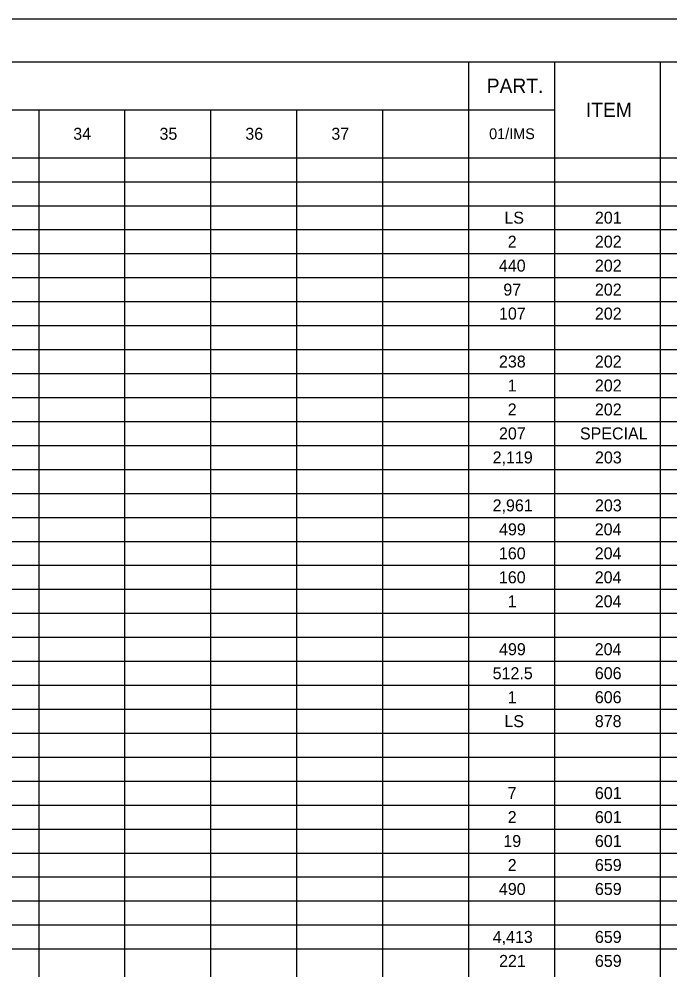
# Model space of a CAD drawing. Extents: x 0 to 34, y 0 to 22.
# Drawn here: x 9.31 to 16.92, y 10.89 to 22 of the extents above; entities that cross this region are included whole.
import ezdxf

# ---------------------------------------------------------------- set-up
doc = ezdxf.new("R2010")
doc.units = 0
for name, color, linetype in [('SH_Border', 7, 'Continuous'), ('SH_Cut_Line', 7, 'Continuous'), ('SH_Data', 7, 'Continuous'), ('SH_Text', 7, 'Continuous')]:
    doc.layers.add(name, color=color, linetype=linetype)

msp = doc.modelspace()

# ---------------------------------------------------------------- linework, layer by layer
at = {"layer": 'SH_Border'}
msp.add_lwpolyline([(1.5, 21.5), (33.5, 21.5), (33.5, 0.5), (1.5, 0.5)], close=True, dxfattribs=at)
at = {"layer": 'SH_Cut_Line'}
msp.add_lwpolyline([(0, 0), (34, 0), (34, 22), (0, 22)], close=True, dxfattribs=at)
at = {"layer": 'SH_Data'}
for p, q in [((1.5, 21.5), (32.004, 21.5)), ((14.561, 21.5), (14.561, 0.5)), ((15.566, 21.5), (15.566, 0.5)), ((16.801, 21.5), (16.801, 0.5)), ((1.5, 20.94), (15.566, 20.94)), ((9.538, 20.94), (9.538, 0.5)), ((10.542, 20.94), (10.542, 0.5)), ((11.547, 20.94), (11.547, 0.5)), ((12.552, 20.94), (12.552, 0.5)), ((13.556, 20.94), (13.556, 0.5)), ((1.5, 20.38), (32.004, 20.38)), ((1.5, 20.1), (32.004, 20.1)), ((1.5, 19.82), (32.004, 19.82)), ((1.5, 19.54), (32.004, 19.54)), ((1.5, 19.26), (32.004, 19.26)), ((1.5, 18.98), (32.004, 18.98)), ((1.5, 18.7), (32.004, 18.7)), ((1.5, 18.42), (32.004, 18.42)), ((1.5, 18.14), (32.004, 18.14)), ((1.5, 17.86), (32.004, 17.86)), ((1.5, 17.58), (32.004, 17.58)), ((1.5, 17.3), (32.004, 17.3)), ((1.5, 17.02), (32.004, 17.02)), ((1.5, 16.74), (32.004, 16.74)), ((1.5, 16.46), (32.004, 16.46)), ((1.5, 16.18), (32.004, 16.18)), ((1.5, 15.9), (32.004, 15.9)), ((1.5, 15.62), (32.004, 15.62)), ((1.5, 15.34), (32.004, 15.34)), ((1.5, 15.06), (32.004, 15.06)), ((1.5, 14.78), (32.004, 14.78)), ((1.5, 14.5), (32.004, 14.5)), ((1.5, 14.22), (32.004, 14.22)), ((1.5, 13.94), (32.004, 13.94)), ((1.5, 13.66), (32.004, 13.66)), ((1.5, 13.38), (32.004, 13.38)), ((1.5, 13.1), (32.004, 13.1)), ((1.5, 12.82), (32.004, 12.82)), ((1.5, 12.54), (32.004, 12.54)), ((1.5, 12.26), (32.004, 12.26)), ((1.5, 11.98), (32.004, 11.98)), ((1.5, 11.7), (32.004, 11.7)), ((1.5, 11.42), (32.004, 11.42)), ((1.5, 11.14), (32.004, 11.14))]:
    msp.add_line(p, q, dxfattribs=at)

# ---------------------------------------------------------------- texts
at = {"layer": 'SH_Text'}
for s, height, p in [('PART.', 0.168, (14.774, 21.136)), ('ITEM', 0.168, (15.933, 20.856)), ('34', 0.14, (9.942, 20.59)), ('35', 0.14, (10.95, 20.59)), ('36', 0.14, (11.953, 20.59)), ('37', 0.14, (12.958, 20.59)), ('01/IMS', 0.126, (14.802, 20.597)), ('LS', 0.14, (14.98, 19.61)), ('201', 0.14, (16.038, 19.61)), ('2', 0.14, (15.019, 19.33)), ('202', 0.14, (16.038, 19.33)), ('440', 0.14, (14.916, 19.05)), ('202', 0.14, (16.038, 19.05)), ('97', 0.14, (14.968, 18.77)), ('202', 0.14, (16.038, 18.77)), ('107', 0.14, (14.917, 18.49)), ('202', 0.14, (16.038, 18.49)), ('238', 0.14, (14.917, 17.93)), ('202', 0.14, (16.038, 17.93)), ('1', 0.14, (15.019, 17.65)), ('202', 0.14, (16.038, 17.65)), ('2', 0.14, (15.019, 17.37)), ('202', 0.14, (16.038, 17.37)), ('207', 0.14, (14.917, 17.09)), ('SPECIAL', 0.14, (15.863, 17.09)), ('2,119', 0.14, (14.843, 16.81)), ('203', 0.14, (16.039, 16.81)), ('2,961', 0.14, (14.843, 16.25)), ('203', 0.14, (16.039, 16.25)), ('499', 0.14, (14.918, 15.97)), ('204', 0.14, (16.036, 15.97)), ('160', 0.14, (14.916, 15.69)), ('204', 0.14, (16.036, 15.69)), ('160', 0.14, (14.916, 15.41)), ('204', 0.14, (16.036, 15.41)), ('1', 0.14, (15.019, 15.13)), ('204', 0.14, (16.036, 15.13)), ('499', 0.14, (14.918, 14.57)), ('204', 0.14, (16.036, 14.57)), ('512.5', 0.14, (14.843, 14.29)), ('606', 0.14, (16.037, 14.29)), ('1', 0.14, (15.019, 14.01)), ('606', 0.14, (16.037, 14.01)), ('LS', 0.14, (14.98, 13.73)), ('878', 0.14, (16.037, 13.73)), ('7', 0.14, (15.018, 12.89)), ('601', 0.14, (16.038, 12.89)), ('2', 0.14, (15.019, 12.61)), ('601', 0.14, (16.038, 12.61)), ('19', 0.14, (14.968, 12.33)), ('601', 0.14, (16.038, 12.33)), ('2', 0.14, (15.019, 12.05)), ('659', 0.14, (16.038, 12.05)), ('490', 0.14, (14.916, 11.77)), ('659', 0.14, (16.038, 11.77)), ('4,413', 0.14, (14.844, 11.21)), ('659', 0.14, (16.038, 11.21)), ('221', 0.14, (14.918, 10.93)), ('659', 0.14, (16.038, 10.93))]:
    msp.add_text(s, height=height, dxfattribs=at).set_placement(p)

doc.saveas('drawing.dxf')
